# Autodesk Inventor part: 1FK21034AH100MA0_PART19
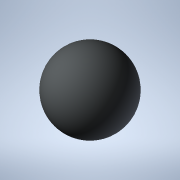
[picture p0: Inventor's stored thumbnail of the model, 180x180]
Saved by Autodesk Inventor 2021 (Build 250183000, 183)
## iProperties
Created: 2025-04
Part Number: 1FK21034AH100MA0_PART19
Material: Generic
Catalog Web Link: www.3dfindit.com
Description: -Servo synchronous motor
Document SubType Name: Modeling
Designer: psAdmin
Mass: 0.113097 g
Surface Area: 1.13097 cm^2
Volume: 0.113097 cm^3
Density: 1 g/cm^3
Appearance: PSOLRGB-212-217-219
Category: PARTsolutions
Title: 1FK21034AH100MA0_PART19
Author: Cadenas PARTsolutions
Comments: Servo synchronous motor
Sending System: PARTsolutions
Preprocessor: ST-DEVELOPER v19.3
PSOL_IDENT_0: {$CADENAS_DATA/23d-libs/siemens_ag/_cat_/39/97/1fk21034ah100ma0.prj},216 {VTYP=3D},{NB=1FK21034AH100
PSOL_IDENT_1: MA0_PART19},{LINA=1FK21034AH100MA0_PART19},{NN=1FK21034AH100MA0_PART19},{NOPRJ=TRUE},{DATE=19.08.202
PSOL_IDENT_2: 5 14:00:33},{GEOMDATE=30.07.2025 02:02:21},{VERSION=},{LINEID=10},{WBVAR=},{WBNUMERIC=}  {NB=1FK2103
PSOL_IDENT_3: 4AH100MA0_PART19},{LINA=1FK21034AH100MA0_PART19},{KT=DUMMY},{PREVIEW=../../../_pool_/d3/78/p_d211_xx
PSOL_IDENT_4: _00934j.png},{DESCSHORT=SIMOTICS S-1FK2 HD, SINAMICS S210 3AC 400V-480V, 1.01 Nm, 4500 rpm},{DESCLON
PSOL_IDENT_5: G=SIMOTICS S-1FK2 HD servo motor M0=1.27 Nm; PN = 0.48 kW at nN=4500 rpm (380-480 V); PN = 0.3 kW at
PSOL_IDENT_6: nN=2500 rpm (200-240 V); with holding brake; degree of protection IP64; cylindrical shaft D14 x 30
PSOL_IDENT_7: mm; absolute encoder 22-bit + 12-bit multiturn (encoder AM22DQC); with OCC interface; plug size M17,
PSOL_IDENT_8: rotatable; SIMOTICS S-1FK2 servomotorfor a wide range of uses in industrial environments. SIMOTICS
PSOL_IDENT_9: S‑1FK2 servomotors are compact synchronous motors with a high dynamic performance that set themselve
PSOL_IDENT_10: s apart as a result of their high power density, degree of protection and overload capability. The m
PSOL_IDENT_11: otors are available in two variants: as High Dynamic variant (highest dynamic performance as a resul
PSOL_IDENT_12: t of the low intrinsic moment of inertia for applications demanding a high dynamic performance with
PSOL_IDENT_13: low moved masses) - and as Compact variant (precise and stable closed-loop control for medium up to
PSOL_IDENT_14: large moved masses as a result of a medium intrinsic moment of inertia). SIMOTICSS‑1FK2 servomotors
PSOL_IDENT_15: fully exploit their strengths in a system with the SINAMICSS210 frequency converter and simple conne
PSOL_IDENT_16: ction using the one cable connection (OCC). Advantages include the short control and positioning tim
PSOL_IDENT_17: es, fast and precise correction of disturbing quantities as well as stable control with a high dynam
PSOL_IDENT_18: ic performance. The servo motors can be configured to address a wide range of requirements. For exam
PSOL_IDENT_19: ple with and without holding brake, IP64 or IP65 degree of protection, singleturn or multiturn absol
PSOL_IDENT_20: ute encoders - to name just a few. Further, the servomotors are available in different shaft heights
PSOL_IDENT_21: extending from 20 to 100. A shaft sealing ring is available to achieve an IP65 degree of protection
PSOL_IDENT_22: and for subsequent mounting at the motor or as spare part. SIMOTICS - the optimum motor for each an
PSOL_IDENT_23: d every motion control application.},{INTNO=195125454019},{SUPPLIERALTNO=1FK2103-4AH10-0MA0},{MANUID=
PSOL_IDENT_24: 1FK21034AH100MA0},{MANUNAME=Siemens},{MANUTYPEDESC=SYNCHRONOUS MOTOR 1FK2 HD 1,27 NM},{AAU732=SIMOTI
PSOL_IDENT_25: CS},{AAO057=S-1FK2},{AAU734=SIMOTICS S-1FK2 HD servo motor M0=1.27 Nm; PN = 0.48 kW at nN=4500 rpm (
PSOL_IDENT_26: 380-480 V); PN = 0.3 kW at nN=2500 rpm (200-240 V); with holding brake; degree of protection IP64; c
PSOL_IDENT_27: ylindrical shaft D14 x 30 mm; absolute encoder 22-bit + 12-bit multiturn (encoder AM22DQC); with OCC
PSOL_IDENT_28: interface; plug size M17, rotatable;},{AAW338=SYNCHRONOUS MOTOR 1FK2 HD 1,27 NM},{AAO742=SIMOTICS},
PSOL_IDENT_29: {AAO663=4034106444921},{NOCUPEROU=1},{PRICEQUANTITY=1},{QUANTITYMIN=1},{QUANTITYINT=1},{CTN=85015100
PSOL_IDENT_30: },{COO=RO},{AAO676=1FK2103-4AH10-0MA0},{AAO677=Siemens AG},{ORDERUNIT=C62},{CONTENTUNIT=C62}
NB: 1FK21034AH100MA0_PART19
NT: Servo synchronous motor
NBSYN: $MANUID._PART19
LINA: 1FK21034AH100MA0_PART19
CATALOG: SIEMENS
PREVIEW: ../../../_pool_/d3/78/p_d211_xx_00934j.png
DESCSHORT: SIMOTICS S-1FK2 HD, SINAMICS S210 3AC 400V-480V, 1.01 Nm, 4500 rpm
DESCLONG: SIMOTICS S-1FK2 HD servo motor M0=1.27 Nm; PN = 0.48 kW at nN=4500 rpm (380-480 V); PN = 0.3 kW at nN=2500 rpm (200-240 V); with holding brake; degree of protec
INTNO: 195125454019
SUPPLIERALTNO: 1FK2103-4AH10-0MA0
MANUID: 1FK21034AH100MA0
MANUNAME: Siemens
MANUTYPEDESC: SYNCHRONOUS MOTOR 1FK2 HD 1,27 NM
AAU732: SIMOTICS
AAO057: S-1FK2
AAU734: SIMOTICS S-1FK2 HD servo motor M0=1.27 Nm; PN = 0.48 kW at nN=4500 rpm (380-480 V); PN = 0.3 kW at nN=2500 rpm (200-240 V); with holding brake; degree of protec
AAW338: SYNCHRONOUS MOTOR 1FK2 HD 1,27 NM
AAO742: SIMOTICS
AAO663: 4034106444921.0
NOCUPEROU: 1
PRICEQUANTITY: 1
QUANTITYMIN: 1
QUANTITYINT: 1
CTN: 85015100
COO: RO
ARTICLENO: 1FK21034AH100MA0_PART19
BOMINFO: 1FK21034AH100MA0_PART19
CREATOR: CADENAS GmbH
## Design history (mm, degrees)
feature "2025_04_17_15_09_00_0361"
body "Solid1"
